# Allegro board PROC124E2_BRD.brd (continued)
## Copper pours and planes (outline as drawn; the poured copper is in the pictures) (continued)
VCC_3V3_SYS on BOTTOM: 39.61,149.28 39.61,147.46 40.04,147.04 42.95,147.04 43.15,146.85 44.82,146.85 45.02,146.64 45.02,146.29 45.15,146.16 45.15,143.57 45.76,142.96 48.17,142.96 49.17,143.97 49.17,150.78 41.1,150.78
VCC_3V3_SYS on BOTTOM: 19.29,136.31 19.29,134.65 20.69,134.65 20.69,136.31
VCC_3V3_SYS on BOTTOM: 11.26,135.37 11.26,134.76 13.8,134.76 13.8,135.37
VCC_3V3_SYS on BOTTOM: 12.46,53.25 14.03,53.25 14.03,51.73 13.7,51.73 13.7,51.16 12.46,51.16
VCC_3V3_SYS on BOTTOM: 15.87,126.62 15.87,123.6 16.02,123.46 17.23,123.46 17.51,123.17 17.51,122.77 18.65,122.77 19.03,123.15 19.03,126.62
VCC_3V3_SYS on BOTTOM: 59.74,87.29 59.74,88.19 60.22,88.68 60.94,88.68 61.34,89.09 61.34,89.48 62.45,89.48 62.45,87.36 61.04,87.36 60.97,87.29
VCC_3V3_SYS on L05_PWR02: 0.53,154.64 84.47,154.64 84.47,5.61 0.53,5.61 ; 8 cut-outs
VCC_5V0 on TOP: 73.08,136.94 73.08,135.83 73.19,135.72 74.52,135.72 74.52,135.72 77.66,135.72 77.66,137.48 77.62,137.52 76.56,137.52 76.04,137 73.13,137
VCC_5V0 on TOP: 19.86,32.82 21.22,32.82 21.82,32.22 22.92,32.22 22.92,31.35 22.56,31 16.57,31 16.57,38.16 19.57,38.16 19.57,33.1
VCC_5V0 on TOP: 64.87,71.18 66.36,71.18 66.45,71.09 66.45,67.11 68.05,67.11 68.4,67.46 70.98,67.46 70.98,66.05 70.59,65.66 65.15,65.66 64.87,65.94
VCC_5V0 on BOTTOM: 21.35,39.7 21.35,36.82 22.74,35.42 22.74,31.25 22.44,30.95 19.19,30.95 18.78,31.35 18.78,33.93 18.63,34.08 16.75,34.08 16.75,35.05 16.45,35.35 16.45,39.7
VCC_5V0 on L04_PWR01: 0.78,138.72 11.69,138.72 12.96,137.45 12.96,112.81 8.11,107.96 8.11,91.17 7.27,91.17 6.39,90.28 6.39,83.8 6.38,83.81 6.38,39.55 20.05,39.55 20.05,32.75 19.95,32.65 16.72,32.65 16.72,35.38 15.88,36.22 10.53,36.22 10.53,33.31 9.86,32.65 7.38,32.65 7.25,32.78 0.78,32.78
VCC_5V0 on L04_PWR01: 64.19,136.89 64.09,136.98 56.79,136.98 55.58,135.76 55.58,126.11 52.53,123.06 52.53,119.28 52.63,119.18 58.34,119.18 58.34,120.9 64.74,120.9 66.07,119.58 66.07,115.39 64.11,113.44 64.11,97.77 65.57,97.77 66.41,96.94 66.41,83.75 63.17,80.51 63.17,65.8 71.54,65.8 71.54,67.54 70.46,67.54 70.46,134.5 78.62,134.5 78.62,136.69 78.42,136.89 75.96,136.89
VCC_5V0 on L05_PWR02: 16.62,34.32 16.62,39.02 23.15,39.02 24.42,37.75 29.7,37.75 29.96,37.5 52.56,37.5 54.34,35.72 61.07,35.72 66.79,41.44 68.82,43.47 68.82,71.41 71.49,71.41 71.49,41.31 68.95,38.77 68.92,38.77 61.44,31.29 41.37,31.29 37.94,34.72 36.32,34.72 35.93,34.32
VCC_5V0_HDMICONN on BOTTOM: 6.82,120.33 9.01,120.33 9.01,118.4 9.59,118.4 9.64,118.35 9.64,117.71 9.56,117.64 9.08,117.64 9.05,117.66 8.04,117.66 8.04,119.44 6.82,119.44
VCC_CORE on TOP: 13.45,90.08 11.03,90.08 10.91,89.95 10.91,85.76 12.68,85.76 13.19,85.25 15.48,85.25 15.48,86.93 13.67,86.93 13.45,87.16
VCC_CSI_IO on TOP: 80.69,136.78 80.63,136.84 80.63,138.89 80.72,138.98 81.64,138.98 81.64,146.41 81.25,146.8 77.8,146.8 77.39,147.21 77.39,149.62 77.37,149.62 77.37,151.47 79.12,151.47 79.12,150.05 78.82,149.75 78.82,148.05 79.12,147.75 82.04,147.75 82.41,147.39 82.41,138.81 82.44,138.78 82.44,136.89 82.33,136.78
VDD1_LPDDR4_1V8 on TOP: 31.1,82.97 31.58,83.44 31.58,83.93 30.39,83.93 29.93,84.39 29.93,85.56 30.04,85.67 31.52,85.67 31.58,85.73 31.58,86.16 31.49,86.26 29.69,86.26 28.11,84.68 27.04,84.68 27.04,82.97
VDD1_LPDDR4_1V8 on BOTTOM: 34.16,87.05 34.7,87.05 34.83,86.92 34.83,85 34.66,84.84 34.15,84.84 33.95,85.04 33.95,86.84
VDD1_LPDDR4_1V8 on L03_SIG1: 29.89,84.83 32.15,84.83 32.59,85.27 35.02,85.27 35.33,84.97 36.59,84.97 36.9,85.27 38.6,85.27 39.16,84.72 41.24,84.72 42.89,86.37 43.73,86.37 43.9,86.2 43.9,77.76 42.63,76.49 30.53,76.49 29.47,77.55 29.47,84.41
VDD_1V0 on BOTTOM: 55.44,90.2 55.09,90.55 55.09,91.42 55.09,91.42 55.94,91.42 56.25,91.73 58.28,91.73 58.28,90.2
VDD_1V0 on L05_PWR02: 55.99,90.46 55.99,91.22 57.01,92.24 57.01,94.78 56.75,95.03 55.99,95.03 55.99,96.68 57.13,97.82 59.42,97.82 60.56,98.97 60.56,99.73 61.2,99.73 62.32,98.61 65.44,98.61 66.07,99.24 66.07,112.9 54.97,112.9 54.91,112.85 53.67,112.85 53.19,113.33 53.19,114.68 53.2,114.69 53.2,116.33 53.43,116.56 57.28,116.56 60.58,119.86 60.58,122.35 62.66,122.35 68.33,116.69 68.33,114.88 69.44,113.77 69.44,96.9 66.81,94.27 64.63,94.27 61.33,90.97 57.77,90.97 57.26,90.46
VDD_1V2 on BOTTOM: 15.78,113.93 15.78,112.86 15.12,112.2 13.6,112.2 13.47,112.07 13.47,104.63 9.61,100.77 6.89,100.77 6.44,101.23 6.44,103.82 8.44,105.83 11.69,105.83 12.4,106.54 12.4,112.33 13.04,112.96 15.07,112.96 15.07,114.11 15.61,114.11
VDD_1V2 on BOTTOM: 15.33,114.36 15.33,113.09 17.69,113.09 17.69,114.69 15.66,114.69
VDD_1V2 on BOTTOM: 9.13,124.34 9.13,122.93 11.47,122.93 11.47,121.85 11.54,121.78 12.46,121.78 12.48,121.8 12.48,123.4 12.67,123.59 12.67,124.29 12.62,124.34
VDD_1V2 on L06_SIG2: 7.86,101.91 7.86,94.93 7.3,94.37 6,94.37 4.51,92.87 4.51,90.56 12.17,82.9 12.17,75.68 13.66,74.19 17.64,74.19 17.64,70.72 7.85,70.72 6.79,71.78 6.79,84.9 1.81,89.87 1.81,100.01 4.1,102.29 7.48,102.29
VDD_2V5 on TOP (solid shape): 66.01,116.59 66.01,115.92 65.13,115.92 64.47,116.58 64.47,117.28 65.32,117.28
VDD_2V5 on TOP: 64.47,94.73 65.32,94.73 66.05,93.99 66.05,93.42 66,93.37 65.13,93.37 64.47,94.03
VDD_2V5 on BOTTOM: 56.88,83.33 56.88,83.4 56.83,83.4 52.38,87.84 52.38,90.43 52.64,90.69 54.75,90.69 54.75,90.41 54.57,90.24 53.17,90.24 52.99,90.06 52.99,88.32 55.46,85.86 56.88,85.86 59.11,85.86 59.11,85.13 60.66,85.13 60.66,83.33
VDD_2V5 on L04_PWR01: 57.57,84.92 57.57,83.27 57.77,83.07 64.96,83.07 65.77,83.88 65.77,97.12 63.42,99.47 63.42,113.28 65.79,115.65 65.79,119.43 64.85,120.37 58.75,120.37 58.75,84.92
VDD_CANUART on L05_PWR02: 31.92,101.83 31.92,101.89 31.86,101.89 31.48,101.51 28.43,101.51 25.13,98.21 21.96,98.21 21.96,98.97 23.23,100.24 24.62,100.24 27.54,103.16 32.37,103.16 33.37,102.15 33.37,101.76 31.99,101.76
VDD_CORE on TOP: 17.51,87.28 17.51,90.08 13.83,90.08 13.83,87.28
VDD_CORE on TOP: 20.34,108.75 20.34,106.84 22.72,106.84 22.72,108.18 22.15,108.75
VDD_CORE on BOTTOM: 14.94,89.54 14.94,88.86 15.05,88.76 18.4,88.76 18.55,88.91 18.55,89.54 18.45,89.65 15.05,89.65
VDD_CORE on BOTTOM: 20.18,108.75 20.18,106.84 22.84,106.84 22.84,108.75
VDD_CORE on L05_PWR02: 13.83,88.47 13.83,103.92 19.42,109.51 24.37,109.51 27.67,112.81 35.04,112.81 39.35,108.49 39.35,101.38 36.05,101.38 33,104.43 33,106.33 32.37,106.97 27.42,106.97 18.91,98.46 18.91,87.28 15.01,87.28
VDD_LPDDR4 on TOP: 21.45,73.69 21.45,77.5 31.12,77.5 31.37,77.75 32.22,77.75 32.34,77.63 32.34,77.43 31.85,76.94 30.16,76.94 29.69,76.47 29.7,76.47 29.7,73.69
VDD_LPDDR4 on L04_PWR01: 33.28,102.17 33.28,100.85 32.78,100.34 28.53,100.34 26.78,98.59 26.78,88.94 28.94,86.79 28.94,73.95 29.32,73.57 40.12,73.57 44.31,77.76 44.31,96.05 43.16,97.19 42.4,97.19 41.39,98.21 41.39,99.09 40.09,100.39 35.67,100.39 35.67,102.4 33.51,102.4
VDD_MMC1 on TOP: 6.51,99.09 6.51,100.33 4.39,100.33 4.39,99.09
VDD_MMC1_SD on TOP: 2.27,97.11 2.27,98.76 2.8,98.76 3.08,99.04 3.08,99.31 3.97,99.31 3.97,98.76 6.21,98.76 6.21,97.11
VDDA1V8 on TOP: 14.21,74.58 13.07,73.44 13.07,72.17 15.73,72.17 15.73,73.57 14.84,74.46 14.84,75.98 14.46,76.36 14.46,77.12 14.21,77.12
VDDA_1V8 on TOP: 12.94,71.66 12.94,68.23 15.73,68.23 15.73,71.66
VDDA_1V8 on BOTTOM: 48.7,112.61 48.73,112.63 50.65,112.63 50.65,110.97 50.83,110.79 50.83,106.35 50.75,106.27 48.84,106.27 48.7,106.42
VDDA_1V8 on L04_PWR01: 13.07,70.27 25.89,70.27 28.81,73.19 40.37,73.19 44.81,77.62 44.81,90.84 46.09,92.12 46.09,94.52 43.04,97.57 42.15,97.57 41.51,98.21 41.51,99.22 40.12,100.62 38.97,100.62 38.97,104.68 39.23,104.94 46.14,104.94 47.63,106.43 47.63,106.43 48.62,107.42 50.85,107.42 50.85,95.18 50.66,93.44 47.16,89.95 47.16,77.18 41.51,71.54 30.46,71.54 27.16,68.23 13.07,68.23
VDDA_1V8_FB1 on BOTTOM: 46.8,115.02 46.8,111.92 48.4,111.92 48.4,115.02
VDDA_1V8_FB1 on L03_SIG1: 33.39,100.62 38.47,100.62 38.47,103.54 38.85,103.92 38.85,107.16 36.94,107.16 36.94,104.43 36.68,104.16 36.68,103.02 35.54,101.89 33.39,101.89
VDDA_1V8_FB1 on L04_PWR01: 32.24,107.86 32.24,109.64 30.42,109.64 29.98,109.2 29.98,106.06 31.73,104.3 33.77,104.3 34.8,105.33 36.35,105.33 36.35,103.48 37.83,103.48 37.83,106.08 41.13,109.38 46.47,109.38 48.54,111.45 48.54,114.21 40.88,114.21 36.05,109.38 36.05,108.75 35.17,107.86
VDDA_1V8_FB2 on BOTTOM: 48.47,103.91 48.47,104.42 48.45,104.43 48.45,108.13 47.27,108.13 47.27,104.2 47.73,103.74 48.3,103.74
VDDA_1V8_FB2 on L04_PWR01: 47.1,106.66 47.1,106.66 49.1,108.66 49.1,109.83 48.66,110.27 46.59,110.27 46.49,110.17 46.49,109.1 46.47,109.07 41.08,109.07 37.73,105.72 37.73,102.37 37.75,102.35 38.72,102.35 38.72,104.81 39.27,105.36 45.8,105.36
VDDA_1V8_FB_OSC on L05_PWR02: 32.77,101.6 32.26,101.09 32.26,98.18 43.09,98.18 43.67,98.76 43.67,102.96 47.78,107.06 47.78,110.9 42.22,110.9 41.61,110.3 41.61,99.68 41.56,99.63 34.25,99.63 34.07,99.81 34.07,101.6
VDDA_DDR_PLL0 on BOTTOM: 17.46,93.25 17.46,90.03 17.66,89.82 19.72,89.82 19.77,89.87 19.77,90.89 19.44,91.22 18.17,91.22 18.17,92.29 18.78,92.9 18.78,92.97 18.25,93.51 17.71,93.51
VDDA_DDR_PLL0 on L03_SIG1: 35.51,102.27 35.51,103.4 33.5,103.4 33.51,103.41 31.99,103.41 31.35,102.78 31.67,102.46 28.97,102.46 29.04,102.53 25.83,102.53 25.31,102.02 27.34,102.02 26.46,101.14 24.43,101.14 19.29,96 19.29,94.81 17.62,93.14 17.49,93.01 17.49,92.39 17.59,92.29 18.1,92.29 20.3,94.5 20.3,95 25.66,100.36 27.03,100.36 27.97,101.3 32.41,101.3 33.39,102.27
VDDC_1V2 on L04_PWR01: 59.06,22.93 59.06,17.77 58.5,17.2 50.68,17.2 50.43,16.95 50.43,14.5 50.68,14.26 60.11,14.26 60.69,14.84 60.69,22.99 60.51,23.17 59.31,23.17
VDDR_CORE on TOP: 6.86,73.06 6.86,70.27 10.78,70.27 10.78,73.06
VDDR_CORE on TOP: 16.93,105.09 16.93,103.69 18.32,103.69 18.32,103.84 20.05,103.84 20.08,103.87 20.08,105.09
VDDR_CORE on L03_SIG1: 35.8,103.41 35.29,103.92 30.33,103.92 30.35,103.9 29.16,103.9 27.44,105.62 27.44,105.65 26.5,106.59 21.39,106.59 18.94,104.14 16.74,104.14 16.47,104.41 16.47,106.31 17.36,107.19 17.36,107.2 23.1,107.2 23.12,107.22 23.12,107.48 27.88,107.48 28.25,107.11 29.12,107.11 30.21,106.01 31.43,106 32.45,104.99 33.73,104.99 33.73,104.98 34.78,104.98 35.11,105.32 35.11,106.36 36.5,106.36 36.5,104.11 36.45,104.06 36.45,103.41
VDDR_CORE on L04_PWR01: 6.65,70.54 6.65,75.13 10.35,78.83 10.35,84.36 11.62,85.63 11.81,85.63 11.81,101.97 15.41,105.56 19.45,105.56 19.45,104.25 16.62,101.42 16.62,82.69 16.37,82.69 14.56,80.88 14.63,80.82 14.63,76.33 8.72,70.42 6.77,70.42
VDDSHV_CANUART on BOTTOM: 20.13,90.69 20.13,89.85 20.2,89.77 23.45,89.77 23.61,89.93 23.61,90.93 20.37,90.93
VDDSHV_CANUART on L04_PWR01: 33.13,101.02 33.13,101.66 32.9,101.89 28.11,101.89 22.72,96.49 22.72,90.06 23.99,90.06 23.99,96.05 28.76,100.82 32.93,100.82
VDDSHV_SDIO on TOP: 9.02,84.87 9.02,83.56 10.27,83.56 10.27,84.87
VDDSHV_SDIO on L04_PWR01: 9.51,83.61 9.51,86.39 8.49,87.41 8.49,95.92 10.14,97.57 11.16,97.57 11.16,98.46 10.78,98.84 8.75,98.84 7.35,97.44 7.35,88.07 7.67,87.75 7.67,83.79 7.99,83.47 9.37,83.47
(no net) on TOP: 64.47,117.28 65.32,117.28 66.01,116.59 66.01,115.92 65.13,115.92 64.47,116.58
(no net) on TOP: 0.53,5.61 0.53,154.64 84.47,154.64 84.47,5.61 ; 170 cut-outs
(no net) on BOTTOM: 76.66,130.63 76.66,128.03 76.77,127.93 77.13,127.93 77.13,127.92 78.51,127.92 78.51,128.78 78.07,128.78 77.89,128.96 77.89,130.55 77.77,130.67 76.7,130.67
(no net) on BOTTOM: 0.53,5.61 0.53,105.52 2.62,105.52 2.62,125.9 0.53,125.9 0.53,154.64 84.47,154.64 84.47,5.61 ; 190 cut-outs
(no net) on BOTTOM: 70.87,108.58 70.87,105.98 70.97,105.88 71.34,105.88 71.34,105.87 73.28,105.87 73.43,106.02 73.43,106.68 73.38,106.73 72.27,106.73 72.1,106.91 72.1,108.5 71.98,108.62 70.91,108.62
(no net) on BOTTOM: 76.05,108.22 76.05,105.62 76.16,105.52 76.52,105.52 76.52,105.51 78.46,105.51 78.61,105.66 78.61,106.32 78.56,106.38 77.46,106.38 77.28,106.55 77.28,108.14 77.16,108.26 76.09,108.26
(no net) on L03_SIG1: 0.51,154.67 84.49,154.67 84.49,5.59 0.51,5.59 ; 208 cut-outs
(no net) on L06_SIG2: 0.51,154.67 84.49,154.67 84.49,5.59 0.51,5.59 ; 143 cut-outs
CPSW1_GPIO_0 on BOTTOM: 81.51,86.89 81.51,84.29 81.62,84.18 81.82,84.18 81.98,84.03 81.98,83.11 82.05,83.03 82.67,83.03 82.74,83.1 82.74,86.81 82.62,86.92 81.55,86.92
CPSW1_LED_1000 on BOTTOM: 82.38,101.66 82,102.04 82,103.55 81.66,103.89 81.66,108.46 82.83,108.46 82.83,105.97 83.98,104.81 83.98,101.66
CPSW1_LED_ACT on BOTTOM: 78.85,86.87 78.85,84.39 78.93,84.31 79.89,84.31 79.97,84.39 79.97,86.81 79.91,86.87 78.85,86.87
CPSW2_GPIO_0 on BOTTOM (solid shape): 77.28,108.14 77.28,106.55 77.46,106.38 77.65,106.38 77.65,106.37 78.57,106.37 78.6,106.34 78.6,105.65 78.46,105.51 76.52,105.51 76.52,105.52 76.16,105.52 76.05,105.62 76.05,108.22 76.09,108.26 77.16,108.26
CPSW2_LED_1000 on BOTTOM (solid shape): 77.89,130.55 77.89,128.96 78.07,128.78 78.51,128.78 78.51,127.92 77.13,127.92 77.13,127.93 76.77,127.93 76.66,128.03 76.66,130.62 77.82,130.62
CPSW2_LED_ACT on BOTTOM (solid shape): 72.1,108.5 72.1,106.91 72.27,106.73 72.47,106.73 72.47,106.73 73.39,106.73 73.43,106.68 73.43,106.02 73.28,105.87 71.34,105.87 71.34,105.88 70.97,105.88 70.87,105.98 70.87,108.58 70.91,108.62 71.98,108.62
DRAIN1 on TOP: 17.69,47.96 17.69,45.35 19.47,45.35 19.47,47.96
DRAIN1 on BOTTOM: 17.91,48.06 18.02,47.94 19.13,47.94 19.22,48.03 19.22,48.85 19.25,48.88 19.47,48.88 19.5,48.86 19.5,45.37 17.77,45.37 17.62,45.53 17.62,47.99 17.53,48.07 17.53,48.86 16.34,50.05 16.34,50.25 18.02,50.25 18.02,49.64 17.91,49.53
DRAIN2 on TOP: 17.69,45.02 17.69,42.25 19.42,42.25 19.42,45.02
DRAIN2 on BOTTOM: 17.95,42.35 18,42.4 19.15,42.4 19.22,42.33 19.22,41.44 19.5,41.44 19.5,44.96 17.77,44.96 17.62,44.81 17.62,41.48 17.63,41.48 17.63,41.43 17.95,41.43
ETH1_EARTH on TOP, L02GND01: 74.61,102.2 74.61,90.79 73.42,89.6 73.42,85.66 73.68,85.4 83.97,85.4 84.42,85.85 84.42,104.55 84.09,104.88 73.93,104.88 73.93,102.88
ETH1_EARTH on BOTTOM: 73.68,85.4 73.42,85.66 73.42,89.6 74.61,90.79 74.61,102.2 73.93,102.88 73.93,104.88 84.09,104.88 84.42,104.55 84.42,85.85 83.97,85.4 ; 3 cut-outs
ETH2_EARTH on TOP, L04_PWR01, L05_PWR02, L07_GND02: 74.61,113.07 72.44,110.9 72.44,108.59 73.07,107.95 83.97,107.95 84.42,108.4 84.42,127.1 84.09,127.43 73.93,127.43 73.93,125.59 74.61,124.91
ETH2_EARTH on BOTTOM: 74.61,124.76 74.61,113.35 73.42,112.16 73.42,112.06 72.44,111.08 72.44,108.59 73.07,107.95 83.97,107.95 84.42,108.4 84.42,127.1 84.09,127.43 73.25,127.43 73.25,126.12 ; 1 cut-out
ETH2_EARTH on L02GND01: 74.61,124.91 74.61,113.07 72.44,110.9 72.44,108.59 73.07,107.95 83.97,107.95 84.42,108.4 84.42,127.1 84.09,127.43 73.93,127.43 73.93,125.59
ETH2_EARTH on L03_SIG1: 74.61,124.91 74.61,113.04 72.44,110.87 72.44,108.59 73.07,107.95 83.97,107.95 84.42,108.4 84.42,127.1 84.09,127.43 73.93,127.43 73.93,125.59
ETH2_EARTH on L06_SIG2: 74.61,113.07 72.44,110.9 72.44,108.59 73.07,107.95 83.97,107.95 84.42,108.4 84.42,127.1 84.09,127.43 73.93,127.43 73.93,125.6 74.61,124.92
ETH_CAN_INH on TOP: 18.39,98.99 18.39,97.04 18.96,97.04 18.96,97.95 19.06,98.05 19.85,98.05 19.85,98.41 19.03,98.41 18.98,98.46 18.98,98.99
FT4232_USB_VBUS on TOP: 9.28,17.84 4.97,17.84 4.97,18.53 5.69,19.25 9.28,19.25
FT4232_USB_VBUS on BOTTOM: 9.23,11.44 9.74,11.44 9.74,10.55 9.87,10.42 9.87,9.1 9.72,8.95 7.94,8.95 7.71,9.18 7.71,13.85 7.41,14.16 7.41,17.36 7,17.76 7,18.83 7.35,19.19 9.26,19.19 9.61,18.83 9.61,17.92 9.23,17.54
HDMI_EARTH on TOP, BOTTOM, L02GND01, L07_GND02: 4.6,125.59 5.9,124.28 8.54,124.28 8.54,121.98 3.26,121.98 3.26,109.79 8.5,109.79 8.5,105.84 0.48,105.84 0.48,125.59
LDO_3V3 on L04_PWR01: 15.63,46.16 15.63,45.45 15.83,45.25 19.15,45.25 19.36,45.46 19.36,50.42 19.62,50.68 24.34,50.68 24.67,50.35 24.67,47.86 25.03,47.51 34.53,47.51 35.7,48.68 35.7,52.26 35.44,52.51 17.59,52.51 17.04,51.96 17.04,46.71 16.55,46.21 15.68,46.21
LM61460_SW on BOTTOM: 33.55,45.77 33.55,44.73 36.68,44.73 37.38,44.03 37.38,42.64 37.69,42.33 39.35,42.33 39.35,48 37.63,48 37.35,47.72 37.35,46.52 36.6,45.77
LVDS_SHIELD on BOTTOM: 59.07,79.36 59.07,81.58 64.68,81.58 64.68,79.36
LVDS_SHIELD on BOTTOM: 58.28,58.81 58.28,57.65 64.23,57.65 64.23,58.81
MIC_IN on BOTTOM: 77.51,45.43 77.51,44.86 77.62,44.75 78.13,44.75 78.35,44.53 78.35,41.94 79.71,41.94 79.71,45.01 79.29,45.43
SOC_DVDD1V8 on TOP: 23.48,80.3 28.18,80.3 28.18,82.58 26.91,82.58 26.4,83.09 23.48,83.09
SOC_DVDD1V8 on L04_PWR01: 16.67,79.99 15.71,80.96 15.71,81.82 15.69,81.82 16.27,82.41 16.85,82.41 17.63,83.19 17.63,96.8 22.72,101.89 22.72,101.89 27.48,106.65 27.48,109.55 30.41,112.48 33.23,112.48 34.12,111.59 34.12,110.02 34.78,109.36 34.78,108.31 32.37,108.31 32.37,109.37 31.81,109.93 30.49,109.93 29.72,109.16 29.72,105.61 30.46,105.19 31.69,103.96 33.91,103.96 34.42,104.47 35.28,104.47 37.61,102.14 37.96,102.14 38.59,101.51 38.59,100.87 38.34,100.62 36.31,100.62 35.93,101 35.93,102.27 35.54,102.65 33,102.65 32.62,102.27 28.04,102.27 22.46,96.69 22.46,90.01 23.72,88.75 23.72,85.34 26.27,82.79 26.27,81.97 26.32,81.92 26.32,80.27 26.04,79.99
SOC_DVDD3V3 on TOP: 19.67,90.71 19.67,86.9 21.96,86.9 21.96,89.82 21.07,90.71
SOC_DVDD3V3 on L03_SIG1: 31.81,106.72 31.81,105.85 32.01,105.65 34.05,105.65 34.12,105.57 34.12,105.06 34.15,105.04 34.73,105.04 34.88,105.19 34.88,106.63 34.8,106.72
SOC_DVDD3V3 on L05_PWR02: 32.33,103.45 27.46,103.45 22.21,98.21 22.21,88.43 21.07,87.28 19.16,87.28 19.16,99.32 26.43,106.59 32.62,106.59 33.13,106.08 33.13,104.27 36.02,101.38 39.1,101.38 39.1,102.57 38.97,102.7 38.97,102.7 38.57,102.7 38.22,103.05 38.22,103.86 38.38,104.02 39.18,104.02 39.41,104.25 39.41,105.01 39.35,105.06 39.35,106.21 37.37,108.19 37.37,109.31 38.08,110.02 39.86,110.02 41.46,108.42 41.46,99.73 33.51,99.73 33.51,102.27
UART_SHIELD on TOP: 4.4,23.4 4.4,20 4.68,19.72 6.4,19.72 6.81,20.14 6.81,23.43 4.43,23.43
UART_SHIELD on BOTTOM: 1.14,23.78 7.27,23.78 7.27,21.83 6.81,21.37 6.81,20.14 6.43,19.76 3.95,19.76 3.65,19.45 3.65,14.15 4.03,13.76 6.39,13.76 6.85,13.31 6.85,11.94 6.57,11.66 1.14,11.66
USB_TYPEA_EARTH on BOTTOM: 72.09,79.66 72.09,77.12 77.61,77.12 77.61,67.06 77.36,66.81 72.32,66.81 72.32,64.78 77.02,64.78 77.76,65.52 83.5,65.52 83.5,79.66
USB_TYPEC1_EARTH on TOP: 0.76,39.1 0.76,51.97 1.12,52.33 8.3,52.33 8.73,51.9 8.73,48.68 4.17,48.68 3.77,48.27 3.77,41.57 4.11,41.23 8.35,41.23 8.35,39.1
USB_TYPEC1_EARTH on BOTTOM: 0.76,39.1 0.76,52.68 0.78,52.69 8.38,52.69 8.38,48.68 4.21,48.68 3.68,48.15 3.68,41.66 4.11,41.23 8.35,41.23 8.35,39.1
USB_TYPEC2_EARTH on TOP: 0.76,24.1 0.76,37.68 0.78,37.69 8.73,37.69 8.73,33.68 5.16,33.68 4.94,33.46 4.94,26.56 5.27,26.23 8.35,26.23 8.35,24.1
USB_TYPEC2_EARTH on BOTTOM: 0.76,24.1 0.76,37.68 0.78,37.69 8.45,37.69 8.45,33.68 5.16,33.68 4.94,33.46 4.94,26.56 5.27,26.23 8.35,26.23 8.35,24.1
VHDMI_AVCC_1V2 on BOTTOM: 18.07,113.07 18.07,115 16.62,115 16.62,116.65 17.55,116.65 17.55,115.99 18.22,115.99 18.35,115.86 18.35,115.25 20.05,115.25 20.11,115.31 20.11,116.29 20.37,116.56 20.37,116.61 21.45,116.61 21.45,113.07
VHDMI_CVCC_1V2 on L04_PWR01: 15.12,116.72 13.1,116.72 13.1,130.15 25.64,130.15 25.64,117.79 23.42,117.79 23.43,117.79 22.56,117.79 22.56,118.53 22.79,118.75 23.4,118.75 23.4,126.17 22.87,126.71 20.89,126.71 19.85,125.66 19.85,123 19.67,122.82 15.38,122.82 15.3,122.89 15.02,122.61 15.02,120.96 14.69,120.63 14.26,120.63 14.18,120.56 14.18,119.19 14.26,119.11 15.12,119.11
VHDMI_IOVCC_3V3 on BOTTOM: 19.19,125.74 19.19,124.62 22.31,124.62 22.31,126.4 21.55,126.4 21.55,125.74
VHDMI_IOVCC_3V3 on L04_PWR01: 21.64,126.2 23.49,126.2 23.49,112.88 21.02,112.88 21.02,119.29 16.21,119.29 15.88,119.62 15.63,119.62 15.63,119.61 14.5,119.61 14.39,119.73 14.39,120.35 15.05,120.35 15.53,120.84 15.53,121.77 15.77,122.01 19.53,122.01 21.64,124.12
VLDO_CSI_1V8 on TOP: 77.97,137.51 77.97,137.18 77.97,137.18 79.12,137.18 79.51,136.79 80.36,136.79 80.36,137.51 80.32,137.55 79.67,137.55 79.63,137.51
VLDO_CSI_3V3 on TOP: 77.96,137.71 77.97,137.7 79.14,137.7 79.54,138.1 80.32,138.1 80.32,138.11 80.32,138.82 80.32,138.83 78.31,138.83 77.96,138.48
VMAIN on TOP: 14.01,42.67 16.35,42.67 16.35,40.78 15.14,39.57 14.05,39.57 14.01,39.61
VMAIN on TOP: 15.01,47.45 15.13,47.32 16.37,47.32 16.37,46.35 13.94,46.35 13.9,46.3 12.12,46.3 11.99,46.43 11.99,47.35 12.09,47.45
VMAIN on TOP: 24.98,32.47 24.98,31.53 26.22,30.29 31.35,30.29 31.35,39.91 29.7,41.56 27.04,41.56 27.04,38.13 28.18,36.99 28.18,32.47
VMAIN on BOTTOM: 28.6,32.29 28.6,30.13 32.05,30.13 32.05,32.29
VMAIN on BOTTOM: 16.59,43.08 17.39,43.08 17.39,41.88 16.36,40.86 15.39,40.86 15.3,40.94 15.3,42.56 15.45,42.7 16.21,42.7
VMAIN on BOTTOM: 32.49,41.56 33.39,42.45 33.39,44.36 34.63,44.36 34.63,37.75 27.04,37.75 27.04,41.56
VMAIN on BOTTOM: 14.95,47.22 14.95,46.49 15.04,46.39 17.36,46.39 17.36,47.08 16.43,47.08 16.18,47.33 15.06,47.33
VMAIN on BOTTOM: 46.11,10.63 46.47,10.63 46.47,9.66 46.85,9.28 46.85,7.33 46.55,7.02 44.49,7.02 44.49,7.96 45.81,7.96 45.81,9.36 46.11,9.66
VMAIN on BOTTOM: 34.54,52.21 34.54,46.21 33.44,46.21 33.44,47.41 32.96,47.89 32.96,49.59 30.62,49.59 30.62,52.21
VMAIN on L04_PWR01: 26.04,32.39 26.04,7.39 27.25,6.18 46.97,6.18 46.97,10.39 36.09,10.39 31.04,15.44 31.04,32.39
VMAIN on L05_PWR02: 14.84,47.31 16.49,47.31 17.16,47.97 24.68,47.97 28.94,52.23 32.79,52.23 33.49,51.53 33.49,39.13 32.12,37.75 23.93,37.75 22.27,39.4 16.75,39.4 14.84,41.31
VPP_1V8 on TOP: 24.6,90.57 25.61,90.57 25.93,90.89 25.93,91.16 25.71,91.38 25.71,92.37 24.6,92.37
VPP_1V8 on L05_PWR02: 24.5,90.95 24.53,90.92 25.46,90.92 26.91,92.36 29.7,92.36 30.08,92.74 30.08,97.8 31.56,97.8 31.68,97.93 31.68,101.44 31.49,101.63 29.7,101.63 29.19,101.13 28.69,101.13 28.05,100.49 28.05,95.16 26.27,93.38 24.5,93.38
XDS_SHIELD on TOP: 76.65,12.1 76.65,9.28 78.41,9.28 78.41,10.01 80,11.59 83.78,11.59 84.09,11.9 84.09,22.34 83.25,23.17 78.6,23.17 77.41,21.98 77.41,20.03 77.99,19.44 80.61,19.44 81.09,18.96 81.09,13.95 80.89,13.75 78.3,13.75
XDS_USB_VBUS on TOP: 75.29,15.71 80.03,15.71 80.03,15.01 79.28,14.26 76.24,14.26 76.06,14.08 75.29,14.08
XDS_USB_VBUS on BOTTOM: 75.5,14.05 75.38,14.17 75.38,15.78 75.38,15.83 77.17,15.83 77.25,15.91 77.25,17.89 77.02,18.12 76.31,18.12 76.31,18.44 75.49,19.27 73.95,19.27 73.95,24.09 75.22,24.09 75.22,22.76 78.67,22.76 78.67,25.23 79.73,25.23 79.81,25.15 79.81,22.82 79.92,22.71 79.92,21.6 79.68,21.36 78.73,21.36 78.73,14.45 78.34,14.05
XDS_USB_VBUS on L04_PWR01: 57.16,26.65 57.16,25.59 58.33,24.42 73.19,24.42 73.7,23.91 73.7,10.17 72.65,9.12 48.55,9.12 48.22,8.79 48.22,6.96 48.39,6.79 76.83,6.79 78.03,7.99 78.03,21.08 79.92,22.97 79.92,26.2 79.46,26.65
N17253649 on BOTTOM: 46,16.03 47.38,16.03 47.38,13.5 46.98,13.09 46.51,13.09 46.43,13.01 46.15,13.01 46.15,13.08 46,13.23
N17849698 on BOTTOM: 14.82,33.77 18.4,33.77 18.4,30.74 15.48,30.74 15.33,30.9 15.33,32.93 15.15,33.1 14.8,33.1 14.77,33.13 14.77,33.72
N17850096 on TOP: 14.18,34.6 14.18,32.65 14.36,32.47 16.14,32.47 16.27,32.6 16.27,34.6 16.21,34.65 14.23,34.65
N17850096 on BOTTOM: 17.79,30.49 18.68,30.49 18.68,27.42 17.79,27.42
N17850096 on BOTTOM: 16.42,34.07 16.42,34.53 16.3,34.66 14.69,34.66 14.69,34.07
N17936309 on BOTTOM: 12.1,34.14 12.1,33.21 12.68,32.62 13.78,32.62 13.88,32.72 13.88,33.16 14.51,33.16 14.56,33.21 14.56,33.87 14.54,33.89 14.54,34.14
N18904630 on TOP: 15.16,105.29 15.04,105.41 15.04,107.01 16.49,107.01 17.49,108.01 19.97,108.01 19.98,107.99 19.98,106.87 19.95,106.83 17.98,106.83 17.51,106.36 16.72,106.36 16.52,106.16 16.52,105.37 16.44,105.29
N18904815 on TOP: 54.71,51.71 54.71,50.8 54.78,50.73 57.62,50.73 57.63,50.74 57.7,50.67 57.7,50.34 57.75,50.3 58.98,50.3 59.05,50.36 59.05,51.68 58.99,51.74 54.74,51.74
N19361868 on TOP: 15.1,78.9 15.1,78.65 16.49,78.65 16.75,78.39 16.75,77.89 19.16,77.89 19.16,79.16 16.62,79.16 16.37,78.9
N19361874 on TOP: 15.1,79.92 15.1,79.44 18.53,79.44 18.53,81.7 16.62,81.7 16.62,80.55 16.62,80.55 16.62,80.17 16.51,80.06 15.24,80.06
N19361880 on TOP: 13.7,81.7 14.46,81.7 14.46,82.36 15.4,83.3 15.4,84.87 13.12,84.87 13.12,83.32 13.7,82.74
N20506305 on TOP: 24.15,32.32 24.15,25.23 26.17,25.23 26.17,29.8 24.8,31.17 24.8,32.32
N20506307 on TOP: 21.63,29.7 21.63,25.23 23.75,25.23 23.75,32.32 23.12,32.32 23.12,31.2
N22221705 on BOTTOM: 26.49,31.27 26.49,28.83 24.28,26.62 24.28,23.49 28.52,23.49 28.52,28.32 28.27,28.32 28.27,31.27
N22234960 on BOTTOM: 23.09,32.41 23.09,28.8 24.49,28.8 24.49,29.39 24.43,29.44 24.21,29.44 24.21,32.41

Small or netless copper shapes (teardrops, artwork), in the pictures only: 1320 on TOP, 1083 on BOTTOM, 322 on L03_SIG1, 5 on L05_PWR02, 203 on L06_SIG2

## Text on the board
Ref Des/Assembly Bottom: PROC124E2 ASSEMBLY BOTTOM REV E2
Ref Des/Silkscreen Bottom: MICRO_SD | B | C | E | D | F | AUTOMATION HEADER | A | OLDI LVDS
User.Comments: CR_UQFN16_TMUX1574_70X100_0-6_TOP_1 | CR_UQFN16_TMUX1574_70X100_0-6_TOP_2 | CR_INA_BGA_6 | CR_UNNAMED_1 | CR_ETH_114E1_1 | CR_UNNAMED_2 | CR_3_2 | CR_1_9 | CR_1_21 | BOARD NAME: | AM62x LP EVM  BOARD | REV: E2 | DATE: 17/02/23 | DESCRIPTION: | SHEET | OF | 15 | PROC124E2 | SCALE: 1 | TEXAS INSTRUMENTS
Ref Des/Assembly Top: A | PROC124E2 ASSEMBLY TOP REV E2
Ref Des/Silkscreen Top: TYPE-C DRP | TYPE-C PWR | HDMI | UART | DGND | VCC_5V0 | C | D | VCC1V8_SYS | PRU HDR | VMAIN | JTAG_EMU1 | USER EXPN | MCU HDR | VDD_1V0 | B8 | VDD_2V5 | A | MIPI CSI-2 | CPSW PHY-2 | CPSW PHY-1 | VCC3V3_XDS | TYPE-A CON | MIC+HPHONE | JTAG | M.2 Key-E | Wi-Fi | B7 | B0 | B15 | LOW POWER SKEVM | PROC124E2 | AM62x
PAGE_OUTLINE: LAYOUT BY | REVIEWED BY | APPROVED BY | SIGNATURES | RC | KK | ZA | DATE | 170223 | SCALE: | SIZE | D | NONE | TEXAS INSTRUMENTS | AM62x LP EVM  BOARD | SHEET 1 OF 15 | PROC124E2 | Rev | E2
DIMENSION: 18. | 16. | 17. | FOR STACKUP DETAIL MISTRAL-8L-14-2-2022-[0235].PDF SHALL BE REFERRED. | ENSURE UL REGISTERED E-FILE NUMBER SHALL BE PRINTED ON THE PCB SILKSCREEN. | VIA ON PAD SHALL BE RESIN FILLED AND CAP-PLATED. | DETAIL-A
DISPLAY_TOP: 32.725 | BACKING PLATE OUTLINE | NON-PLATED MOUNTING HOLE | 30.225 | SOCKET OUTLINE | 4X | dia | 1.70 | 13.8625 | 8.7825 | 8.0000 | 0 | 0.80 | TYP | 441X | 0.42 | MIN  PADS | 11.3225 | NON-PLATED ALIGNMENT HOLE | 2X | 0.850
User.14: A | TASY PROC100E2_BRD
User.15: A | TASY PROC100E2_BRD
User.17: 2 | 10 | 4 | 6 | 3 | 5 | B1 | 8 | A12 | 74 | 19 | 32 | 43 | 72 | 55 | 16 | 54 | 17 | 64 | 56 | 13 | 14 | 7 | 12 | 9 | 18 | 36 | 49 | 33 | 48 | A | 1 | 20 | 28 | 27 | 11 | 128 | 25 | 97 | 24 | 96 | 50 | 40 | 39 | 42 | 38 | 65 | 22 | 21 | 23 | 75 | 29 | 15 | 37 | CAN RST | DGND | 1V8 | TYPE-C:2 | PMIC | PRG | TYPE-C:1 | FTDI LED | SoC LED | VCC_CORE | 5V0 | PGOOD | 3V3 | MAIN | 0V85 | RST | B7 | VCC1V1 | ERRORn | B0 | B15 | VDDA | XDS110 | 3V3_SYS | MCU_PORz | ETH_CLK_OUT | B8 | EXP LED | WDOG_DIS | PORz | RSTz | REFCLK | 1V0 | 3V3_TA | XDS | USB | 3V3_XDS | L_R+ | L_L+ | M.2 Key-E | 1V2 | SDIO | VPP | SoC INTn | 2V5 | I2C1_SCL | I2C1_SDA | TYPE-C | UART | PWR | DRP | FTDI | MCU HDR | OPN# | SK-AM62A-LP | USER EXPN | BOOTMODE | LPDDR4 | 110 | MIPI CSI-2 | AM62A SKEVM | PROC135E2 | TYPE-A CONN | MIC.HPHONE | RGMII-1 | JTAG | HDMI | VMAIN | JTAG CTI | eMMC | RGMII-2 | CONN | SL# | PROC135E2 ASSEMBLY TOP
User.18: 2 | 50 | 49
User.45: FIGURE | SIZE | 8.0 | 36.0 | 40.0 | 52.0 | 66.0 | 118.0 | 32.0 | 34.0 | 44.0 | 48.0 | 62.0 | 108.0 | 126.0 | 48.0x22.0 | 62.0x24.0 | 68.0x34.0 | 82.0x24.0 | 118.0x28.0 | DRILL CHART: TOP to BOTTOM | ALL UNITS ARE IN MILS | TOLERANCE | +3.0/-3.0 | +3.0/-2.0 | +1.0/-1.0 | +2.0/-2.0 | PLATED | NON-PLATED | QTY | 2718 | 48 | 6 | 81 | 4 | 1 | 2 | 10 | 03 | 04 | 05 | 06 | 07 | STRIPLINE | MICROSTRIP | EDGE COUPLED STRIPLINE | EDGE COUPLED MICROSTRIP | L3,L6 | L1,L8 | 3.8 | 4.35 | 6.8 | 8 | 4.2 | 5.2 | 5.9 | 5.15 | NA | 90 | 40 | 50 | L2/L4,L5/L7 | L2,L7 | 6 - Provide serial numbers to the assembled boards for identification. | 7 - The assembled board are wrapped in ESD Covers(individual) and packed securely before shipment. | ASSEMBLY NOTES:- | 1 - All MSL components should be baked as per JEDEC standard. | 2 - PCB should be baked at 120 degree for 8 hours. | 3 - Board assembly must comply with workmanship standards IPC-A-610 Class 2, unless otherwise specified. | 4 - These assemblies are ESD sensitive, ESD precautions shall be observed. | 5 - These assemblies must be clean and free from flux and all contaminants. Use of no clean flux is not acceptable. | PROC101 E2 ASSEMBLY TOP | PROC101 E2 ASSEMBLY BOTTOM
